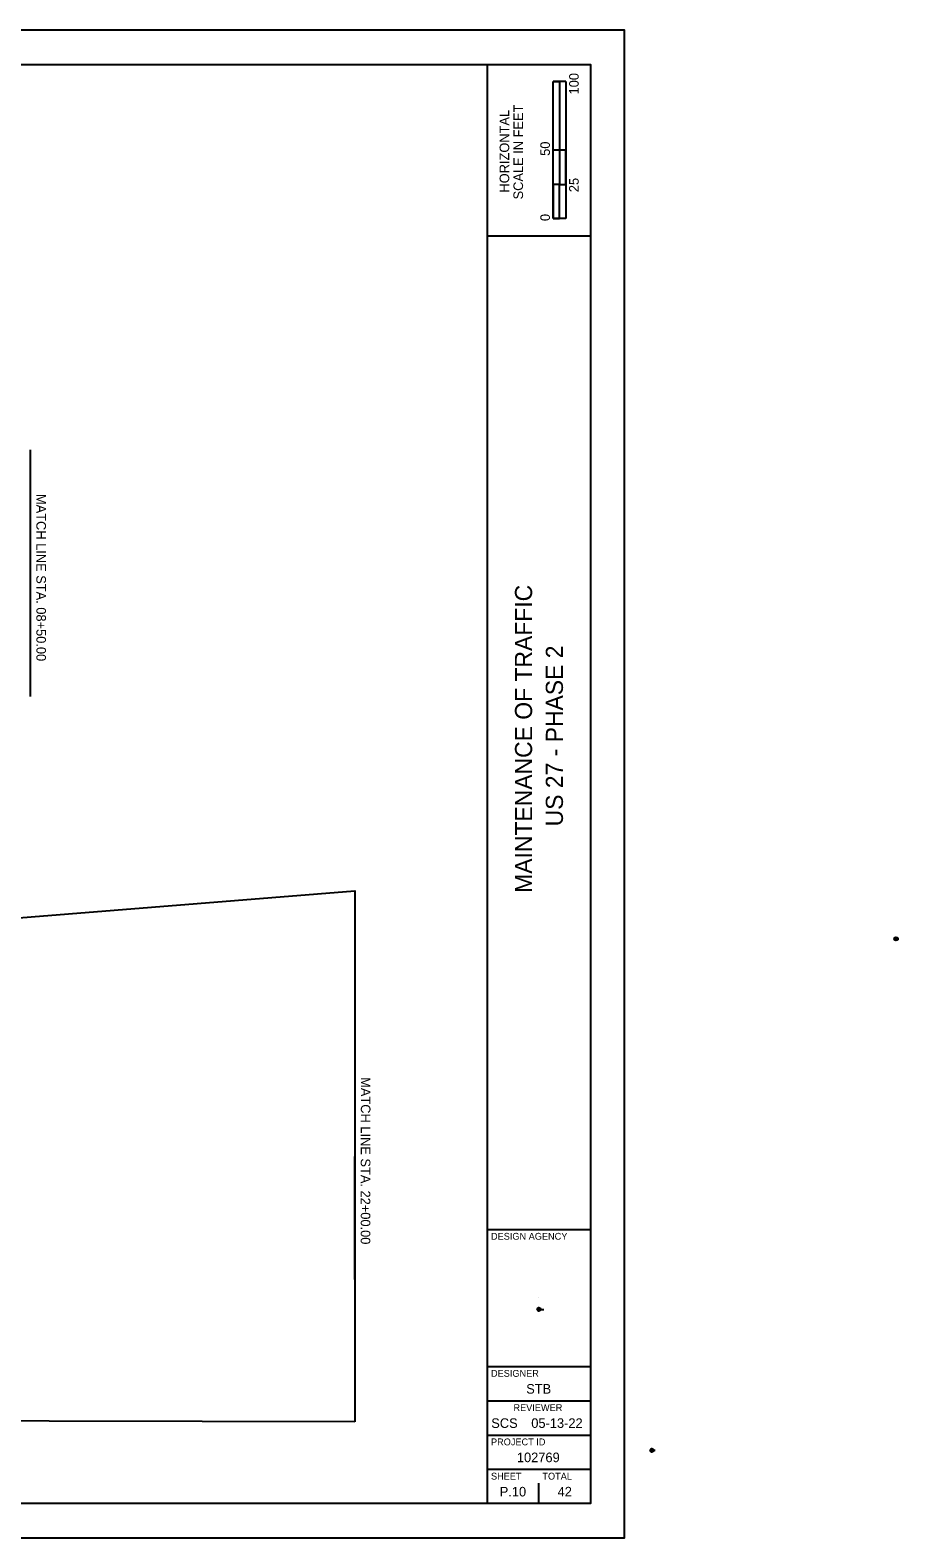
# Model space of a CAD drawing. Extents: x -864 to 1900, y 0 to 1764.
# Drawn here: x 1266 to 1900, y 0 to 1100 of the extents above; entities that cross this region are included whole.
import ezdxf

# ---------------------------------------------------------------- set-up
doc = ezdxf.new("R2010")
doc.units = 0
for name, color, linetype in [('MT_P_Drums', 7, 'Continuous'), ('MT_P_PCB', 7, 'Continuous'), ('MT_P_Traffic_Attenuator', 7, 'Continuous'), ('PV_X_Shoulder', 7, 'Continuous'), ('SH_Border', 7, 'Continuous')]:
    doc.layers.add(name, color=color, linetype=linetype)

msp = doc.modelspace()

# ---------------------------------------------------------------- linework, layer by layer
at = {"layer": 'MT_P_Drums'}
for p, q in [((1647.8, 962.5), (1647.8, 1062.5)), ((1657.2, 1062.5), (1647.8, 1062.5)), ((1647.8, 1012.5), (1647.8, 1062.5)), ((1647.8, 1062.5), (1652.5, 1062.5)), ((1652.5, 1062.5), (1652.5, 1012.5)), ((1652.5, 1062.5), (1652.5, 1062.5)), ((1657.2, 1062.5), (1657.2, 962.5)), ((1652.5, 1012.5), (1647.8, 1012.5)), ((1657.2, 1012.5), (1652.5, 1012.5)), ((1652.5, 1012.5), (1652.5, 987.5)), ((1657.2, 987.5), (1657.2, 1012.5)), ((1652.5, 987.5), (1647.8, 987.5)), ((1647.8, 987.5), (1647.8, 962.5)), ((1652.5, 962.5), (1652.5, 987.5)), ((1652.5, 987.5), (1657.2, 987.5)), ((1657.2, 962.5), (1647.8, 962.5)), ((1647.8, 962.5), (1652.5, 962.5)), ((1637.5, 175), (1637.5, 175)), ((1618.7, 33.8), (1618.7, 33.8)), ((1637.5, 25), (1637.5, 40))]:
    msp.add_line(p, q, dxfattribs=at)
at = {"layer": 'MT_P_PCB'}
for p, q in [((1600, 25), (1600, 1075)), ((1600, 950), (1675, 950)), ((1600, 225), (1675, 225)), ((1600, 125), (1675, 125)), ((1600, 100), (1675, 100)), ((1600, 75), (1675, 75)), ((1600, 50), (1675, 50))]:
    msp.add_line(p, q, dxfattribs=at)
msp.add_lwpolyline([(75, 1075), (1675, 1075), (1675, 25), (75, 25)], close=True, dxfattribs=at)
at = {"layer": 'MT_P_Traffic_Attenuator'}
for p, q in [((1896.6, 437), (1899.2, 437)), ((1897.9, 437), (1900, 437)), ((1636.2, 166.7), (1638.8, 166.7)), ((1637.5, 166.7), (1641.1, 166.7)), ((1718.6, 63.9), (1721.2, 63.9)), ((1719.9, 63.9), (1722.3, 63.9))]:
    msp.add_line(p, q, dxfattribs=at)
msp.add_lwpolyline([(1503.1, 84.7), (165.6, 87.6), (146.9, 363.2), (1503.1, 472.1)], close=True, dxfattribs=at)
for centre in [(1897.9, 437), (1637.5, 166.7), (1719.9, 63.9)]:
    msp.add_circle(centre, 1.3, dxfattribs=at)
at = {"layer": 'PV_X_Shoulder'}
for p, q in [((1266.4, 793.9), (1266.4, 613.9)), ((1503.1, 368.4), (1503, 188.4))]:
    msp.add_line(p, q, dxfattribs=at)
at = {"layer": 'SH_Border'}
msp.add_lwpolyline([(0, 0), (1700, 0), (1700, 1100), (0, 1100)], close=True, dxfattribs=at)

# ---------------------------------------------------------------- texts
at = {"layer": 'MT_P_Drums'}
for s, height, p in [('100', 7, (1666.5, 1053.1)), ('SCALE IN FEET', 7, (1625.9, 976.5)), ('HORIZONTAL', 7, (1615.8, 981.5)), ('50', 7, (1645.5, 1008.3)), ('25', 7, (1666.5, 981.8)), ('0', 7, (1645.5, 960.7)), ('MAINTENANCE OF TRAFFIC', 12.5, (1632.5, 470.6)), ('US 27 - PHASE 2', 12.5, (1655, 519.1))]:
    msp.add_text(s, height=height, rotation=90, dxfattribs=at).set_placement(p)
for s, height, p in [('DESIGN AGENCY', 5, (1602.5, 217.5)), ('DESIGNER', 5, (1602.5, 117.5)), ('STB', 7, (1628.2, 105.2)), ('REVIEWER', 5, (1618.9, 92.5)), ('SCS', 7, (1602.7, 80.2)), ('05-13-22', 7, (1631.9, 80.2)), ('PROJECT ID', 5, (1602.5, 67.5)), ('102769', 7, (1621.4, 55.2)), ('SHEET', 5, (1602.5, 42.5)), ('TOTAL', 5, (1640, 42.5)), ('P.10', 7, (1608.9, 30.2)), ('42', 7, (1651.1, 30.2))]:
    msp.add_text(s, height=height, dxfattribs=at).set_placement(p)
at = {"layer": 'MT_P_Traffic_Attenuator'}
for s, p in [('P.10', (1897.7, 436.5)), ('2', (1897.9, 437.4)), ('Ref', (1899.5, 437.4)), ('1:50', (1899.5, 436.5)), ('P.10', (1637.3, 166.2)), ('4', (1637.4, 167.1)), ('Drawing-1 - Copy-1', (1639.1, 167.1)), ('1:1', (1639.1, 166.2)), ('P.10', (1719.7, 63.4)), ('1', (1719.8, 64.3)), ('Drawing', (1721.5, 64.3)), ('1:50', (1721.5, 63.4))]:
    msp.add_text(s, height=0.164, dxfattribs=at).set_placement(p)
at = {"layer": 'PV_X_Shoulder'}
for s, rotation, p in [('MATCH LINE STA. 08+50.00', 270, (1270.9, 761.6)), ('MATCH LINE STA. 22+00.00', 269.9484, (1507.6, 336.1))]:
    msp.add_text(s, height=7, rotation=rotation, dxfattribs=at).set_placement(p)

doc.saveas('drawing.dxf')
